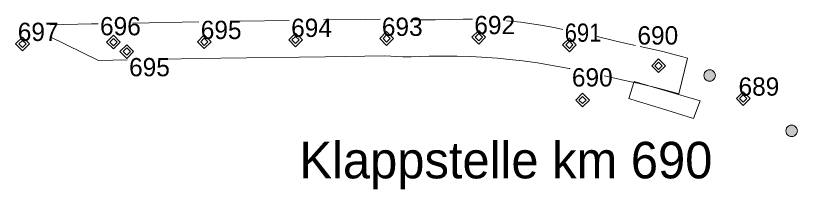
# Model space of a CAD drawing. Extents: x 3461750 to 3585707, y 5917729 to 5985917.
# Drawn here: x 3508911 to 3517468, y 5970523 to 5972426 of the extents above; entities that cross this region are included whole.
import ezdxf

# ---------------------------------------------------------------- set-up
doc = ezdxf.new("R2010")
doc.units = 0
doc.header["$LTSCALE"] = 80
doc.layers.add('11', color=7, linetype='Continuous')
for name, color, linetype, lineweight in [('12', 7, 'Continuous', 13), ('13', 7, 'Continuous', 13), ('14', 7, 'Continuous', 13), ('15', 7, 'Continuous', 13), ('2', 7, 'Continuous', 13), ('3', 7, 'Continuous', 13), ('6', 7, 'Continuous', 13)]:
    doc.layers.add(name, color=color, linetype=linetype, lineweight=lineweight)

msp = doc.modelspace()

# ---------------------------------------------------------------- hatches: boundary and pattern name
at = {"layer": '3'}
for points in [[(3516570.4, 5971769.79), (3516567.47, 5971786.41), (3516561.22, 5971801.5), (3516551.28, 5971814.46), (3516538.32, 5971824.41), (3516523.23, 5971830.66), (3516507.03, 5971832.79), (3516490.84, 5971830.66), (3516475.74, 5971824.41), (3516462.78, 5971814.46), (3516452.84, 5971801.5), (3516446.59, 5971786.41), (3516444.46, 5971770.22), (3516446.59, 5971754.02), (3516452.84, 5971738.93), (3516462.78, 5971725.97), (3516475.74, 5971716.02), (3516490.84, 5971709.77), (3516507.03, 5971707.64), (3516523.23, 5971709.77), (3516538.32, 5971716.02), (3516551.28, 5971725.97), (3516561.22, 5971738.93), (3516567.47, 5971754.02)], [(3517467.91, 5971164.12), (3517464.98, 5971180.75), (3517458.73, 5971195.84), (3517448.79, 5971208.8), (3517435.83, 5971218.74), (3517420.74, 5971224.99), (3517404.54, 5971227.13), (3517388.35, 5971224.99), (3517373.25, 5971218.74), (3517360.29, 5971208.8), (3517350.35, 5971195.84), (3517344.1, 5971180.75), (3517341.97, 5971164.55), (3517344.1, 5971148.36), (3517350.35, 5971133.26), (3517360.29, 5971120.3), (3517373.25, 5971110.36), (3517388.35, 5971104.11), (3517404.54, 5971101.98), (3517420.74, 5971104.11), (3517435.83, 5971110.36), (3517448.79, 5971120.3), (3517458.73, 5971133.26), (3517464.98, 5971148.36)]]:
    msp.add_hatch(color=256, dxfattribs=at).paths.add_polyline_path(points)

# ---------------------------------------------------------------- linework, layer by layer
at = {"layer": '12'}
for points in [[(3510128.01, 5972107.52), (3510052.92, 5972032.43), (3510128.01, 5971957.34), (3510203.1, 5972032.43)], [(3510128.01, 5972072.13), (3510088.32, 5972032.43), (3510128.01, 5971992.74), (3510167.7, 5972032.43)]]:
    msp.add_lwpolyline(points, close=True, dxfattribs=at)
at = {"layer": '13'}
for points in [[(3515116.83, 5971576.76), (3515041.74, 5971501.67), (3515116.83, 5971426.58), (3515191.92, 5971501.67)], [(3515116.83, 5971541.36), (3515077.14, 5971501.67), (3515116.83, 5971461.98), (3515156.52, 5971501.67)]]:
    msp.add_lwpolyline(points, close=True, dxfattribs=at)
at = {"layer": '14'}
for points in [[(3515948.28, 5971952.45), (3515873.18, 5971877.36), (3515948.28, 5971802.27), (3516023.37, 5971877.36)], [(3515948.28, 5971917.05), (3515908.58, 5971877.36), (3515948.28, 5971837.66), (3515987.97, 5971877.36)]]:
    msp.add_lwpolyline(points, close=True, dxfattribs=at)
at = {"layer": '15'}
for points in [[(3512972.44, 5972250.69), (3512897.36, 5972175.6), (3512972.44, 5972100.51), (3513047.54, 5972175.6)], [(3513980.89, 5972264.36), (3513905.8, 5972189.27), (3513980.89, 5972114.18), (3514055.98, 5972189.27)], [(3508986.41, 5972190.43), (3508911.32, 5972115.34), (3508986.41, 5972040.25), (3509061.5, 5972115.34)], [(3509981.97, 5972210.75), (3509906.88, 5972135.66), (3509981.97, 5972060.57), (3510057.06, 5972135.66)], [(3509981.97, 5972175.35), (3509942.27, 5972135.66), (3509981.97, 5972095.96), (3510021.66, 5972135.66)], [(3510976.4, 5972215.04), (3510901.31, 5972139.95), (3510976.4, 5972064.86), (3511051.49, 5972139.95)], [(3510976.4, 5972179.65), (3510936.71, 5972139.95), (3510976.4, 5972100.26), (3511016.09, 5972139.95)], [(3511975.67, 5972234.58), (3511900.58, 5972159.49), (3511975.67, 5972084.4), (3512050.76, 5972159.49)], [(3511975.67, 5972199.18), (3511935.97, 5972159.49), (3511975.67, 5972119.79), (3512015.36, 5972159.49)], [(3512972.44, 5972215.29), (3512932.75, 5972175.6), (3512972.45, 5972135.91), (3513012.14, 5972175.6)], [(3513980.89, 5972228.96), (3513941.2, 5972189.27), (3513980.89, 5972149.58), (3514020.58, 5972189.27)], [(3514972.05, 5972179.99), (3514896.96, 5972104.9), (3514972.05, 5972029.8), (3515047.14, 5972104.9)], [(3508986.41, 5972155.04), (3508946.72, 5972115.34), (3508986.41, 5972075.65), (3509026.1, 5972115.34)], [(3514972.05, 5972144.59), (3514932.36, 5972104.9), (3514972.05, 5972065.2), (3515011.75, 5972104.9)], [(3516875.47, 5971592.78), (3516800.38, 5971517.69), (3516875.47, 5971442.6), (3516950.56, 5971517.69)], [(3516875.47, 5971557.38), (3516835.78, 5971517.69), (3516875.47, 5971478), (3516915.16, 5971517.69)]]:
    msp.add_lwpolyline(points, close=True, dxfattribs=at)
at = {"layer": '2'}
for p, q in [((3510917.7, 5972357.45), (3510188.7, 5972344.04)), ((3513905.81, 5972388.67), (3513865.92, 5972388.67)), ((3513912.1, 5972388.61), (3513905.81, 5972388.67)), ((3509819.19, 5971936.23), (3509288.5, 5972192.63)), ((3510133.2, 5971942.18), (3509819.19, 5971936.23)), ((3513241.8, 5971975.88), (3513150.83, 5971974.9)), ((3516266.94, 5971960.35), (3516171.04, 5971568.55))]:
    msp.add_line(p, q, dxfattribs=at)
for points in [[(3509815.1, 5972337.17), (3509742.72, 5972335.84), (3509288.5, 5972326.22)], [(3511907, 5972373.2), (3511367.33, 5972365.72), (3511291.3, 5972364.32)], [(3512900, 5972387.45), (3512741.26, 5972384.77), (3512280.6, 5972378.38)], [(3513865.92, 5972388.67), (3513809.03, 5972388.67), (3513502.78, 5972381.64), (3513318.21, 5972380.37), (3513273.6, 5972379.43)], [(3514901.3, 5972274.58), (3514805.81, 5972295.51), (3514661.52, 5972321.09), (3514440.14, 5972353.12), (3514285.7, 5972368.37)], [(3515697.1, 5972100.63), (3515547.51, 5972133.4), (3515318.99, 5972186.82), (3515274.9, 5972195.78)], [(3516266.94, 5971960.35), (3516216.02, 5971975.88), (3515980.96, 5972037.11), (3515747.24, 5972089.6)], [(3513150.83, 5971974.9), (3512950.93, 5971986.72), (3512300.2, 5971975.59), (3511155.81, 5971960.45), (3510506.8, 5971948.97)], [(3513887.99, 5971977.15), (3513743.21, 5971981.84), (3513589.31, 5971983.2), (3513437.74, 5971982.13), (3513241.8, 5971975.88)], [(3514980, 5971846.1), (3514971.92, 5971847.75), (3514766.7, 5971884.67), (3514622.71, 5971907.81), (3514462.74, 5971931.54), (3514317.04, 5971947.07), (3514184.52, 5971960.25), (3513950.88, 5971975.1), (3513887.99, 5971977.15)], [(3516171.04, 5971568.55), (3516132.42, 5971580.76), (3515945.85, 5971631.84), (3515736.13, 5971681.64), (3515577.64, 5971716.5), (3515435.55, 5971747.56), (3515353.6, 5971766.05)]]:
    msp.add_lwpolyline(points, dxfattribs=at)
at = {"layer": '3'}
for points in [[(3516570.4, 5971769.79), (3516567.47, 5971786.41), (3516561.22, 5971801.5), (3516551.28, 5971814.46), (3516538.32, 5971824.41), (3516523.23, 5971830.66), (3516507.03, 5971832.79), (3516490.84, 5971830.66), (3516475.74, 5971824.41), (3516462.78, 5971814.46), (3516452.84, 5971801.5), (3516446.59, 5971786.41), (3516444.46, 5971770.22), (3516446.59, 5971754.02), (3516452.84, 5971738.93), (3516462.78, 5971725.97), (3516475.74, 5971716.02), (3516490.84, 5971709.77), (3516507.03, 5971707.64), (3516523.23, 5971709.77), (3516538.32, 5971716.02), (3516551.28, 5971725.97), (3516561.22, 5971738.93), (3516567.47, 5971754.02)], [(3517467.91, 5971164.12), (3517464.98, 5971180.75), (3517458.73, 5971195.84), (3517448.79, 5971208.8), (3517435.83, 5971218.74), (3517420.74, 5971224.99), (3517404.54, 5971227.13), (3517388.35, 5971224.99), (3517373.25, 5971218.74), (3517360.29, 5971208.8), (3517350.35, 5971195.84), (3517344.1, 5971180.75), (3517341.97, 5971164.55), (3517344.1, 5971148.36), (3517350.35, 5971133.26), (3517360.29, 5971120.3), (3517373.25, 5971110.36), (3517388.35, 5971104.11), (3517404.54, 5971101.98), (3517420.74, 5971104.11), (3517435.83, 5971110.36), (3517448.79, 5971120.3), (3517458.73, 5971133.26), (3517464.98, 5971148.36)]]:
    msp.add_lwpolyline(points, close=True, dxfattribs=at)
at = {"layer": '6'}
for points in [[(3515622.02, 5971517.29), (3515681.59, 5971705.47), (3516405.42, 5971491.7), (3516329.88, 5971300.49)], [(3516329.88, 5971300.49), (3515981.35, 5971409.67), (3515713.77, 5971489.65), (3515622.02, 5971517.29)]]:
    msp.add_lwpolyline(points, dxfattribs=at)

# ---------------------------------------------------------------- texts
at = {"layer": '11'}
msp.add_text('Klappstelle km 690 ', height=400, dxfattribs=at).set_placement((3512018.3, 5970644.1))
at = {"layer": '12'}
msp.add_text('695', height=200, dxfattribs=at).set_placement((3510153.2, 5971762.1))
at = {"layer": '13'}
msp.add_text('690', height=200, dxfattribs=at).set_placement((3515000, 5971650))
at = {"layer": '14'}
msp.add_text('690', height=200, dxfattribs=at).set_placement((3515717.1, 5972109.6))
at = {"layer": '15'}
for s, p in [('692', (3513932.1, 5972223)), ('697', (3508934.9, 5972148.2)), ('696', (3509835.1, 5972210.6)), ('695', (3510937.7, 5972169.8)), ('694', (3511927, 5972192.6)), ('693', (3512920, 5972204)), ('689', (3516823.7, 5971549.6))]:
    msp.add_text(s, height=200, dxfattribs=at).set_placement(p)
at = {"layer": '15', "width": 0.9}
msp.add_text('691', height=200, dxfattribs=at).set_placement((3514921.3, 5972139.4))

doc.saveas('drawing.dxf')
